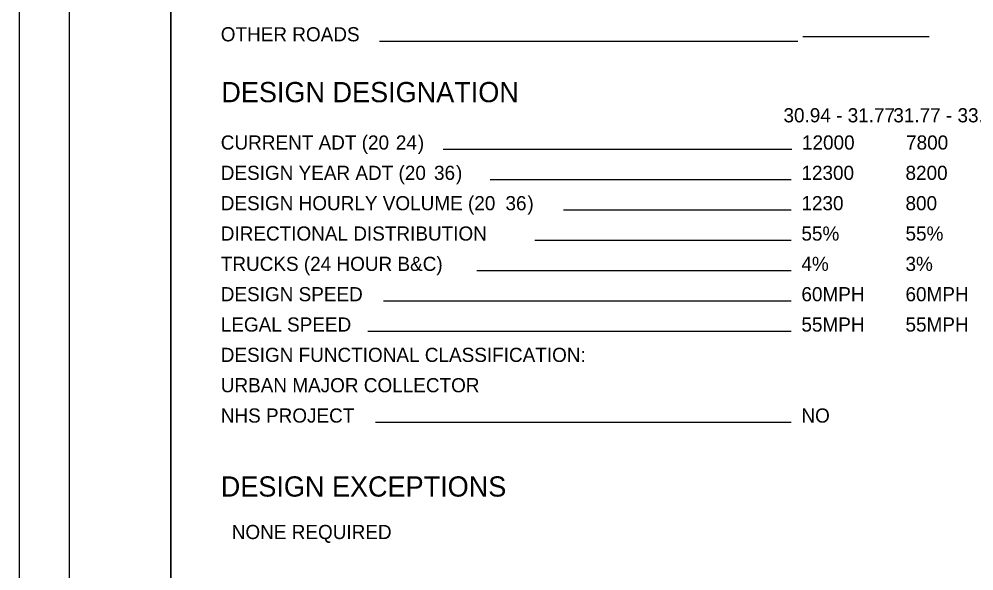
# Model space of a CAD drawing. Extents: x -12 to 34, y 0 to 22.
# Drawn here: x 0 to 9.44, y 5.64 to 11.1 of the extents above; entities that cross this region are included whole.
import ezdxf

# ---------------------------------------------------------------- set-up
doc = ezdxf.new("R2010")
doc.units = 0
for name, color, linetype in [('GM_X_Adjacent_County', 7, 'Continuous'), ('GM_X_County', 7, 'Continuous'), ('GM_X_Section', 7, 'Continuous'), ('GM_X_Township', 7, 'Continuous')]:
    doc.layers.add(name, color=color, linetype=linetype)

msp = doc.modelspace()

# ---------------------------------------------------------------- linework, layer by layer
at = {"layer": 'GM_X_County'}
for points in [[(0.5, 21.5), (1.5, 21.5), (1.5, 0.5), (0.5, 0.5)], [(1.5, 21.5), (33.5, 21.5), (33.5, 0.5), (1.5, 0.5)]]:
    msp.add_lwpolyline(points, close=True, dxfattribs=at)
at = {"layer": 'GM_X_Section'}
msp.add_lwpolyline([(0, 0), (34, 0), (34, 22), (0, 22)], close=True, dxfattribs=at)
at = {"layer": 'GM_X_Township'}
for p, q in [((7.7, 10.8767), (3.5657, 10.8767)), ((9, 10.9223), (7.75, 10.9223)), ((7.6424, 9.8062), (4.1936, 9.8062)), ((7.6368, 9.5062), (4.6592, 9.5062)), ((7.6368, 9.2062), (5.3852, 9.2062)), ((7.6368, 8.9062), (5.0988, 8.9062)), ((7.6368, 8.6062), (4.5259, 8.6062)), ((7.6368, 8.3062), (3.6035, 8.3062)), ((7.6368, 8.0062), (3.4488, 8.0062)), ((7.6368, 7.1062), (3.5243, 7.1062))]:
    msp.add_line(p, q, dxfattribs=at)

# ---------------------------------------------------------------- texts
at = {"layer": 'GM_X_Adjacent_County'}
for s, height, p in [('OTHER ROADS', 0.14, (1.9944, 10.8767)), ('CURRENT ADT (20', 0.14, (1.9944, 9.8062)), ('24', 0.14, (3.7261, 9.8062)), (')', 0.14, (3.9435, 9.8062)), ('12000 ', 0.14, (7.7424, 9.8062)), ('7800  ', 0.14, (8.7718, 9.8062)), ('DESIGN YEAR ADT (20', 0.14, (1.9944, 9.5062)), ('36', 0.14, (4.1033, 9.5062)), (')', 0.14, (4.3207, 9.5062)), ('12300 ', 0.14, (7.7368, 9.5062)), ('8200  ', 0.14, (8.7662, 9.5062)), ('DESIGN HOURLY VOLUME (20', 0.14, (1.9944, 9.2062)), ('36', 0.14, (4.8099, 9.2062)), (')', 0.14, (5.0274, 9.2062)), ('1230  ', 0.14, (7.7368, 9.2062)), ('800   ', 0.14, (8.7662, 9.2062)), ('DIRECTIONAL DISTRIBUTION', 0.14, (1.9944, 8.9062)), ('55%   ', 0.14, (7.7368, 8.9062)), ('55%   ', 0.14, (8.7662, 8.9062)), ('TRUCKS (24 HOUR B&C)', 0.14, (1.9944, 8.6062)), ('4%    ', 0.14, (7.7368, 8.6062)), ('3%    ', 0.14, (8.7662, 8.6062)), ('DESIGN SPEED', 0.14, (1.9944, 8.3062)), ('60MPH ', 0.14, (7.7368, 8.3062)), ('60MPH ', 0.14, (8.7662, 8.3062)), ('LEGAL SPEED', 0.14, (1.9944, 8.0062)), ('55MPH ', 0.14, (7.7368, 8.0062)), ('55MPH ', 0.14, (8.7662, 8.0062)), ('DESIGN FUNCTIONAL CLASSIFICATION:', 0.14, (1.9944, 7.7062)), ('URBAN MAJOR COLLECTOR                           ', 0.14, (1.9944, 7.4062)), ('NHS PROJECT', 0.14, (1.9944, 7.1062)), ('NO    ', 0.14, (7.7368, 7.1062)), ('DESIGN EXCEPTIONS', 0.2, (1.9944, 6.3744)), ('NONE REQUIRED                          ', 0.14, (2.103, 5.9544))]:
    msp.add_text(s, height=height, dxfattribs=at).set_placement(p)
at = {"layer": 'GM_X_Township'}
for s, height, p in [('DESIGN DESIGNATION', 0.2, (2, 10.2747)), ('30.94 - 31.77', 0.14, (7.5594, 10.0756)), ('31.77 - 33.89', 0.14, (8.6455, 10.0756))]:
    msp.add_text(s, height=height, dxfattribs=at).set_placement(p)

doc.saveas('drawing.dxf')
